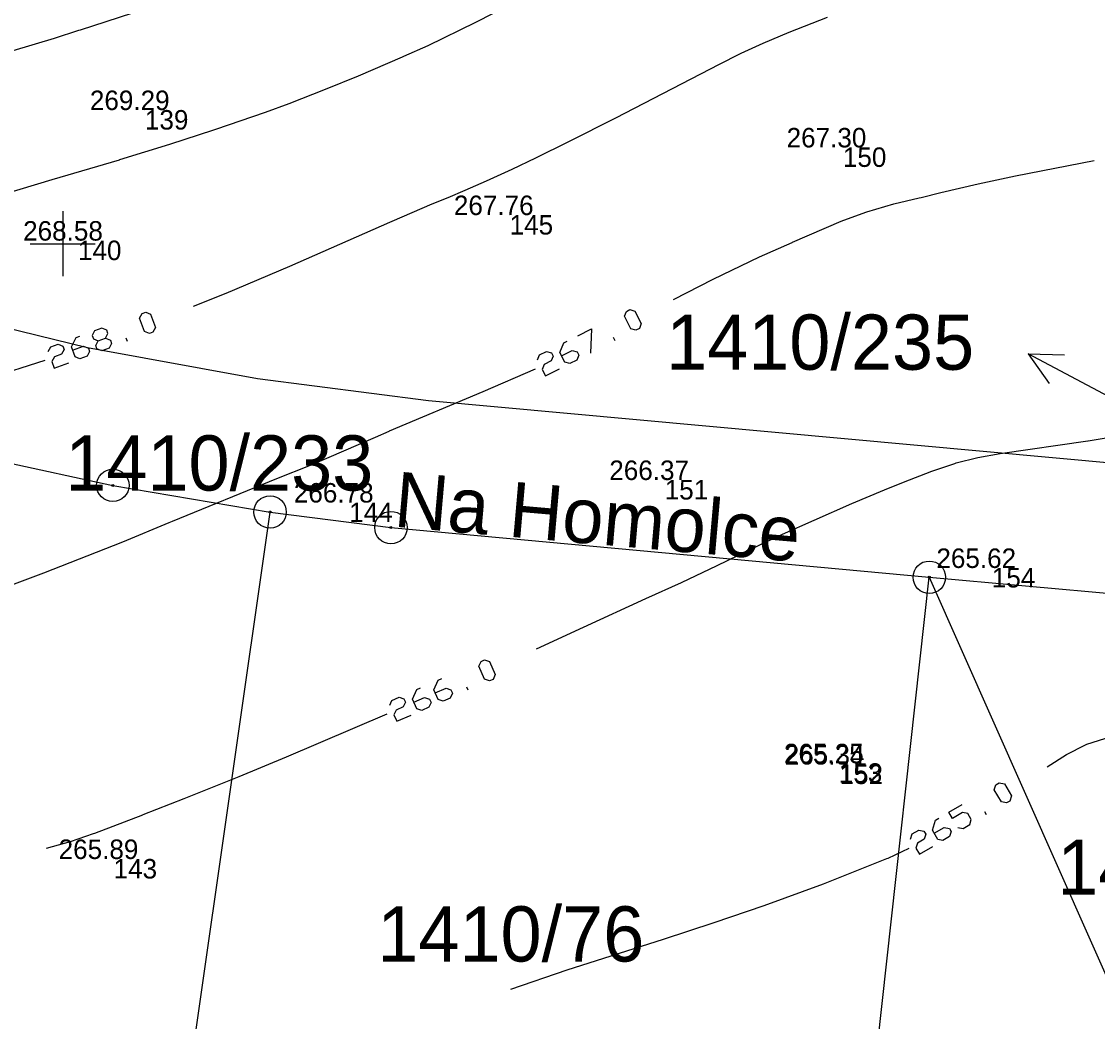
# Model space of a CAD drawing. Extents: x -771260 to -770828, y -1053564 to -1052811.
# Drawn here: x -770951.27 to -770918.15, y -1053323.95 to -1053293.16 of the extents above; entities that cross this region are included whole.
import ezdxf

# ---------------------------------------------------------------- set-up
doc = ezdxf.new("R2010")
doc.units = 0
for name, color, linetype in [('14_8_2023_krizky', 7, 'Continuous'), ('18_8_2023_vrstevnice_po_1m', 7, 'Continuous'), ('18_8_2023_zamereny_bod', 7, 'Continuous'), ('18_8_2023_zamereny_bod_cislo', 7, 'Continuous'), ('18_8_2023_zamereny_bod_vyska', 7, 'Continuous'), ('25_3_2019_krizky_JTSK', 7, 'Continuous'), ('DKM_Hranice parcel', 7, 'Continuous'), ('DKM_Parcelní čísla', 7, 'Continuous'), ('DKM_Pop  PČ popisy', 7, 'Continuous'), ('DKM_Značky bodu BP', 7, 'Continuous')]:
    doc.layers.add(name, color=color, linetype=linetype)

# ---------------------------------------------------------------- blocks, each defined once
blk = doc.blocks.new('KRIZEK')
at = {"layer": '25_3_2019_krizky_JTSK'}
for p, q in [((0, 10), (0, -10)), ((-10, 0), (10, 0))]:
    blk.add_line(p, q, dxfattribs=at)

msp = doc.modelspace()

# ---------------------------------------------------------------- linework, layer by layer
at = {"layer": '18_8_2023_vrstevnice_po_1m'}
for points in [[(-770954.285, -1053299.253), (-770952.368, -1053298.64), (-770952.307, -1053298.621), (-770950.323, -1053298.024), (-770948.256, -1053297.415), (-770948.24, -1053297.41), (-770946.707, -1053296.934), (-770945.355, -1053296.495), (-770945.287, -1053296.473), (-770943.761, -1053295.949), (-770943.036, -1053295.684), (-770941.913, -1053295.246), (-770940.902, -1053294.831), (-770939.542, -1053294.247), (-770939.501, -1053294.23), (-770938.752, -1053293.895), (-770937.285, -1053293.181), (-770934.067, -1053291.521)], [(-770951.525, -1053294.047), (-770950.258, -1053293.667), (-770949.505, -1053293.426), (-770949.459, -1053293.412), (-770946.265, -1053292.365)], [(-770945.973, -1053301.918), (-770944.976, -1053301.519), (-770943.012, -1053300.693), (-770939.938, -1053299.336), (-770939.858, -1053299.301), (-770938.632, -1053298.773), (-770938.143, -1053298.572), (-770937.614, -1053298.355), (-770936.962, -1053298.062), (-770936.173, -1053297.708), (-770935.436, -1053297.356), (-770934.425, -1053296.849), (-770932.98, -1053296.125), (-770929.788, -1053294.47), (-770929.163, -1053294.154), (-770929.12, -1053294.133), (-770928.442, -1053293.82), (-770927.644, -1053293.489), (-770926.464, -1053293.029)], [(-770949.459, -1053293.412), (-770949.459, -1053293.412)], [(-770937.285, -1053293.181), (-770937.285, -1053293.181)], [(-770950.258, -1053293.667), (-770950.258, -1053293.667)], [(-770927.644, -1053293.489), (-770927.644, -1053293.489)], [(-770938.752, -1053293.895), (-770938.752, -1053293.895)], [(-770929.12, -1053294.133), (-770929.12, -1053294.133)], [(-770928.442, -1053293.82), (-770928.442, -1053293.82)], [(-770939.501, -1053294.23), (-770939.501, -1053294.23)], [(-770929.788, -1053294.47), (-770929.788, -1053294.47)], [(-770940.902, -1053294.831), (-770940.902, -1053294.831)], [(-770941.913, -1053295.246), (-770941.913, -1053295.246)], [(-770943.036, -1053295.684), (-770943.036, -1053295.684)], [(-770943.761, -1053295.949), (-770943.761, -1053295.949)], [(-770932.98, -1053296.125), (-770932.98, -1053296.125)], [(-770945.287, -1053296.473), (-770945.287, -1053296.473)], [(-770946.707, -1053296.934), (-770946.707, -1053296.934)], [(-770948.24, -1053297.41), (-770948.24, -1053297.41)], [(-770935.436, -1053297.356), (-770935.436, -1053297.356)], [(-770931.201, -1053301.717), (-770929.979, -1053301.094), (-770928.557, -1053300.407), (-770927.556, -1053299.958), (-770927.538, -1053299.95), (-770926.04, -1053299.304), (-770925.285, -1053299.026), (-770925.248, -1053299.013), (-770924.422, -1053298.772), (-770923.644, -1053298.591), (-770923.585, -1053298.577), (-770922.98, -1053298.419), (-770921.825, -1053298.152), (-770920.676, -1053297.909), (-770918.253, -1053297.44)], [(-770936.173, -1053297.708), (-770936.173, -1053297.708)], [(-770950.323, -1053298.024), (-770950.323, -1053298.024)], [(-770920.676, -1053297.909), (-770920.676, -1053297.909)], [(-770937.614, -1053298.355), (-770937.614, -1053298.355)], [(-770922.98, -1053298.419), (-770922.98, -1053298.419)], [(-770921.825, -1053298.152), (-770921.825, -1053298.152)], [(-770938.632, -1053298.773), (-770938.632, -1053298.773)], [(-770924.422, -1053298.772), (-770924.422, -1053298.772)], [(-770923.585, -1053298.577), (-770923.585, -1053298.577)], [(-770925.248, -1053299.013), (-770925.248, -1053299.013)], [(-770939.858, -1053299.301), (-770939.858, -1053299.301)], [(-770926.04, -1053299.304), (-770926.04, -1053299.304)], [(-770927.538, -1053299.95), (-770927.538, -1053299.95)], [(-770928.557, -1053300.407), (-770928.557, -1053300.407)], [(-770943.012, -1053300.693), (-770943.012, -1053300.693)], [(-770929.979, -1053301.094), (-770929.979, -1053301.094)], [(-770944.976, -1053301.519), (-770944.976, -1053301.519)], [(-770931.201, -1053301.717), (-770931.201, -1053301.717)], [(-770945.973, -1053301.918), (-770945.973, -1053301.918)], [(-770932.362, -1053302.666), (-770932.518, -1053302.623), (-770932.713, -1053302.234), (-770932.655, -1053302.083), (-770932.548, -1053302.029), (-770932.392, -1053302.072), (-770932.197, -1053302.461), (-770932.255, -1053302.612), (-770932.362, -1053302.666)], [(-770947.336, -1053302.762), (-770947.486, -1053302.701), (-770947.635, -1053302.292), (-770947.56, -1053302.149), (-770947.447, -1053302.108), (-770947.297, -1053302.169), (-770947.148, -1053302.578), (-770947.224, -1053302.721), (-770947.336, -1053302.762)], [(-770948.685, -1053302.906), (-770948.61, -1053302.763), (-770948.647, -1053302.661), (-770948.797, -1053302.6), (-770949.022, -1053302.682), (-770949.097, -1053302.825), (-770949.06, -1053302.927), (-770948.91, -1053302.988)], [(-770934.153, -1053302.835), (-770933.725, -1053302.62), (-770933.753, -1053303.365)], [(-770949.697, -1053303.275), (-770949.36, -1053303.152), (-770949.21, -1053303.214), (-770949.173, -1053303.316), (-770949.248, -1053303.459), (-770949.473, -1053303.541), (-770949.623, -1053303.48), (-770949.735, -1053303.173), (-770949.584, -1053302.887), (-770949.472, -1053302.846)], [(-770948.685, -1053302.906), (-770948.535, -1053302.968), (-770948.498, -1053303.07), (-770948.573, -1053303.213), (-770948.798, -1053303.295), (-770948.948, -1053303.234), (-770948.985, -1053303.132), (-770948.91, -1053302.988)], [(-770948.91, -1053302.988), (-770948.685, -1053302.906)], [(-770948.011, -1053303.008), (-770948.048, -1053302.906)], [(-770934.648, -1053303.449), (-770934.327, -1053303.288), (-770934.171, -1053303.331), (-770934.122, -1053303.429), (-770934.18, -1053303.58), (-770934.394, -1053303.687), (-770934.55, -1053303.644), (-770934.697, -1053303.352), (-770934.581, -1053303.05), (-770934.474, -1053302.996)], [(-770933.004, -1053302.988), (-770933.053, -1053302.891)], [(-770950.447, -1053303.317), (-770950.372, -1053303.173), (-770950.147, -1053303.091), (-770949.997, -1053303.153), (-770949.96, -1053303.255), (-770950.035, -1053303.398), (-770950.26, -1053303.48), (-770950.335, -1053303.623), (-770950.261, -1053303.828), (-770949.811, -1053303.664)], [(-770935.388, -1053303.577), (-770935.329, -1053303.426), (-770935.115, -1053303.318), (-770934.96, -1053303.362), (-770934.911, -1053303.459), (-770934.969, -1053303.61), (-770935.183, -1053303.718), (-770935.241, -1053303.869), (-770935.143, -1053304.063), (-770934.715, -1053303.848)], [(-770974.631, -1053307.114), (-770972.984, -1053307.161), (-770971.679, -1053307.169), (-770970.125, -1053307.143), (-770969.042, -1053307.109), (-770967.711, -1053307.046), (-770966.119, -1053306.941), (-770965.025, -1053306.854), (-770963.668, -1053306.722), (-770962.316, -1053306.55), (-770962.296, -1053306.547), (-770960.548, -1053306.286), (-770959.637, -1053306.136), (-770958.795, -1053305.97), (-770958.745, -1053305.961), (-770958.079, -1053305.805), (-770956.948, -1053305.513), (-770955.247, -1053305.029), (-770952.303, -1053304.147), (-770952.291, -1053304.144), (-770950.541, -1053303.583)], [(-770951.818, -1053310.592), (-770950.586, -1053310.133), (-770948.152, -1053309.176), (-770946.723, -1053308.583), (-770946.628, -1053308.543), (-770943.415, -1053307.232), (-770942.372, -1053306.82), (-770942.326, -1053306.802), (-770940.377, -1053305.961), (-770939.957, -1053305.771), (-770939.94, -1053305.763), (-770937.065, -1053304.549), (-770935.45, -1053303.852)], [(-770937.065, -1053304.549), (-770937.065, -1053304.549)], [(-770935.422, -1053312.473), (-770933.975, -1053311.81), (-770932.052, -1053310.928), (-770930.958, -1053310.435), (-770929.86, -1053309.903), (-770928.525, -1053309.257), (-770927.849, -1053308.938), (-770926.876, -1053308.512), (-770925.71, -1053308.002), (-770924.712, -1053307.577), (-770924.123, -1053307.337), (-770923.251, -1053307), (-770922.546, -1053306.764), (-770922.508, -1053306.751), (-770921.835, -1053306.585), (-770921.146, -1053306.462), (-770918.446, -1053306.068), (-770918.439, -1053306.066), (-770915.953, -1053305.663)], [(-770940.377, -1053305.961), (-770940.377, -1053305.961)], [(-770939.94, -1053305.763), (-770939.94, -1053305.763)], [(-770918.439, -1053306.066), (-770918.439, -1053306.066)], [(-770921.835, -1053306.585), (-770921.835, -1053306.585)], [(-770921.146, -1053306.462), (-770921.146, -1053306.462)], [(-770942.326, -1053306.802), (-770942.326, -1053306.802)], [(-770923.251, -1053307), (-770923.251, -1053307)], [(-770922.508, -1053306.751), (-770922.508, -1053306.751)], [(-770943.415, -1053307.232), (-770943.415, -1053307.232)], [(-770924.123, -1053307.337), (-770924.123, -1053307.337)], [(-770924.712, -1053307.577), (-770924.712, -1053307.577)], [(-770925.71, -1053308.002), (-770925.71, -1053308.002)], [(-770946.628, -1053308.543), (-770946.628, -1053308.543)], [(-770927.849, -1053308.938), (-770927.849, -1053308.938)], [(-770948.152, -1053309.176), (-770948.152, -1053309.176)], [(-770928.525, -1053309.257), (-770928.525, -1053309.257)], [(-770950.586, -1053310.133), (-770950.586, -1053310.133)], [(-770930.958, -1053310.435), (-770930.958, -1053310.435)], [(-770932.052, -1053310.928), (-770932.052, -1053310.928)], [(-770935.422, -1053312.473), (-770935.422, -1053312.473)], [(-770936.867, -1053313.46), (-770937.021, -1053313.408), (-770937.195, -1053313.009), (-770937.128, -1053312.862), (-770937.019, -1053312.814), (-770936.866, -1053312.866), (-770936.691, -1053313.265), (-770936.758, -1053313.412), (-770936.867, -1053313.46)], [(-770939.192, -1053314.119), (-770938.863, -1053313.975), (-770938.71, -1053314.027), (-770938.666, -1053314.127), (-770938.732, -1053314.274), (-770938.952, -1053314.37), (-770939.105, -1053314.318), (-770939.236, -1053314.019), (-770939.103, -1053313.724), (-770938.994, -1053313.676)], [(-770938.534, -1053313.832), (-770938.205, -1053313.688), (-770938.052, -1053313.74), (-770938.008, -1053313.839), (-770938.074, -1053313.987), (-770938.294, -1053314.083), (-770938.447, -1053314.031), (-770938.577, -1053313.732), (-770938.445, -1053313.436), (-770938.335, -1053313.389)], [(-770937.526, -1053313.748), (-770937.569, -1053313.648)], [(-770939.938, -1053314.207), (-770939.871, -1053314.059), (-770939.652, -1053313.963), (-770939.499, -1053314.015), (-770939.455, -1053314.115), (-770939.521, -1053314.263), (-770939.741, -1053314.358), (-770939.807, -1053314.506), (-770939.72, -1053314.705), (-770939.281, -1053314.514)], [(-770919.698, -1053316.103), (-770919.111, -1053315.722), (-770918.525, -1053315.431), (-770918.486, -1053315.412), (-770917.731, -1053315.174), (-770916.951, -1053314.984), (-770915.901, -1053314.771), (-770913.248, -1053314.263), (-770911.909, -1053313.966), (-770911.895, -1053313.963)], [(-770950.5, -1053318.613), (-770949.76, -1053318.4), (-770949.056, -1053318.163), (-770949.012, -1053318.148), (-770947.536, -1053317.583), (-770947.524, -1053317.578), (-770946.263, -1053317.085), (-770944.576, -1053316.403), (-770943.112, -1053315.796), (-770940.015, -1053314.478)], [(-770918.486, -1053315.412), (-770918.486, -1053315.412)], [(-770943.112, -1053315.796), (-770943.112, -1053315.796)], [(-770919.111, -1053315.722), (-770919.111, -1053315.722)], [(-770919.698, -1053316.103), (-770919.698, -1053316.103)], [(-770944.576, -1053316.403), (-770944.576, -1053316.403)], [(-770920.951, -1053317.219), (-770921.109, -1053317.186), (-770921.33, -1053316.81), (-770921.282, -1053316.656), (-770921.179, -1053316.595), (-770921.02, -1053316.628), (-770920.8, -1053317.003), (-770920.848, -1053317.158), (-770920.951, -1053317.219)], [(-770946.263, -1053317.085), (-770946.263, -1053317.085)], [(-770922.451, -1053317.975), (-770922.292, -1053318.008), (-770922.086, -1053317.886), (-770922.038, -1053317.732), (-770922.148, -1053317.544), (-770922.307, -1053317.511), (-770922.616, -1053317.693), (-770922.727, -1053317.506), (-770922.314, -1053317.263)], [(-770947.524, -1053317.578), (-770947.524, -1053317.578)], [(-770921.57, -1053317.583), (-770921.625, -1053317.489)], [(-770923.18, -1053318.151), (-770922.871, -1053317.969), (-770922.712, -1053318.002), (-770922.657, -1053318.096), (-770922.705, -1053318.251), (-770922.911, -1053318.372), (-770923.07, -1053318.339), (-770923.235, -1053318.057), (-770923.139, -1053317.748), (-770923.036, -1053317.688)], [(-770949.012, -1053318.148), (-770949.012, -1053318.148)], [(-770923.91, -1053318.328), (-770923.862, -1053318.173), (-770923.655, -1053318.052), (-770923.497, -1053318.085), (-770923.442, -1053318.179), (-770923.49, -1053318.333), (-770923.696, -1053318.455), (-770923.744, -1053318.609), (-770923.634, -1053318.797), (-770923.221, -1053318.554)], [(-770950.5, -1053318.613), (-770950.5, -1053318.613)], [(-770949.76, -1053318.4), (-770949.76, -1053318.4)], [(-770936.208, -1053322.947), (-770934.475, -1053322.361), (-770931.513, -1053321.41), (-770929.949, -1053320.898), (-770928.415, -1053320.375), (-770926.582, -1053319.712), (-770924.639, -1053318.933), (-770924.6, -1053318.917), (-770923.954, -1053318.607)], [(-770924.6, -1053318.917), (-770924.6, -1053318.917)], [(-770926.582, -1053319.712), (-770926.582, -1053319.712)], [(-770928.415, -1053320.375), (-770928.415, -1053320.375)], [(-770929.949, -1053320.898), (-770929.949, -1053320.898)], [(-770931.513, -1053321.41), (-770931.513, -1053321.41)], [(-770934.475, -1053322.361), (-770934.475, -1053322.361)], [(-770936.208, -1053322.947), (-770936.208, -1053322.947)]]:
    msp.add_lwpolyline(points, dxfattribs=at)
at = {"layer": '18_8_2023_zamereny_bod'}
for p, q in [((-770947.472, -1053295.885), (-770947.472, -1053295.885)), ((-770925.99, -1053297.035), (-770925.99, -1053297.035)), ((-770936.247, -1053299.118), (-770936.247, -1053299.118)), ((-770949.533, -1053299.904), (-770949.533, -1053299.904)), ((-770931.475, -1053307.275), (-770931.475, -1053307.275)), ((-770941.183, -1053307.969), (-770941.183, -1053307.969)), ((-770921.407, -1053309.983), (-770921.407, -1053309.983)), ((-770926.116, -1053315.997), (-770926.116, -1053315.997)), ((-770926.092, -1053316.036), (-770926.092, -1053316.036)), ((-770948.436, -1053318.944), (-770948.436, -1053318.944))]:
    msp.add_line(p, q, dxfattribs=at)
at = {"layer": 'DKM_Hranice parcel'}
for p, q in [((-770938.74, -1053304.83), (-770910.45, -1053307.41)), ((-770947.02, -1053332.05), (-770943.62, -1053308.26)), ((-770925.69, -1053331.62), (-770923.33, -1053310.27)), ((-770923.33, -1053310.27), (-770911.93, -1053311.29)), ((-770923.33, -1053310.27), (-770914.09, -1053331.12))]:
    msp.add_line(p, q, dxfattribs=at)
for points in [[(-770987.56, -1053285.59), (-770984.56, -1053287.74), (-770983.25, -1053288.69), (-770981.02, -1053290.15), (-770978.77, -1053291.54), (-770975.07, -1053293.62), (-770974.14, -1053294.15), (-770969.37, -1053296.5), (-770964.48, -1053298.58), (-770959.49, -1053300.4), (-770954.4, -1053301.93), (-770949.24, -1053303.19), (-770944.01, -1053304.15), (-770938.74, -1053304.83)], [(-770965.04, -1053302.65), (-770962.01, -1053303.78), (-770958.66, -1053304.87), (-770955.3, -1053305.85), (-770951.86, -1053306.71), (-770948.46, -1053307.44), (-770943.62, -1053308.26)], [(-770943.62, -1053308.26), (-770939.9, -1053308.74), (-770923.33, -1053310.27)]]:
    msp.add_lwpolyline(points, dxfattribs=at)
at = {"layer": 'DKM_Pop  PČ popisy'}
for p, q in [((-770917.64, -1053304.8), (-770920.29, -1053303.391)), ((-770920.29, -1053303.391), (-770919.17, -1053303.419)), ((-770920.29, -1053303.391), (-770919.641, -1053304.303))]:
    msp.add_line(p, q, dxfattribs=at)
at = {"layer": 'DKM_Značky bodu BP'}
for centre, radius in [((-770948.46, -1053307.44), 0.5), ((-770948.46, -1053307.44), 0.0303), ((-770943.62, -1053308.26), 0.5), ((-770943.62, -1053308.26), 0.0303), ((-770939.9, -1053308.74), 0.5), ((-770939.9, -1053308.74), 0.0303), ((-770923.33, -1053310.27), 0.5), ((-770923.33, -1053310.27), 0.0303)]:
    msp.add_circle(centre, radius, dxfattribs=at)

# ---------------------------------------------------------------- block references
at = {"layer": '14_8_2023_krizky', "xscale": 0.1, "yscale": 0.10000000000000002}
msp.add_blockref('KRIZEK', (-770950, -1053300), dxfattribs=at)

# ---------------------------------------------------------------- texts
at = {"layer": '18_8_2023_zamereny_bod_cislo'}
for s, p in [('139', (-770947.472, -1053296.485)), ('150', (-770925.99, -1053297.635)), ('145', (-770936.247, -1053299.718)), ('140', (-770949.533, -1053300.504)), ('151', (-770931.475, -1053307.875)), ('144', (-770941.183, -1053308.569)), ('154', (-770921.407, -1053310.583)), ('153', (-770926.116, -1053316.597)), ('152', (-770926.092, -1053316.636)), ('143', (-770948.436, -1053319.544))]:
    msp.add_text(s, height=0.6, dxfattribs=at).set_placement(p)
at = {"layer": '18_8_2023_zamereny_bod_vyska'}
for s, p in [('269.29 ', (-770949.166, -1053295.885)), ('267.30 ', (-770927.722, -1053297.035)), ('267.76 ', (-770937.963, -1053299.118)), ('268.58 ', (-770951.221, -1053299.904)), ('266.37 ', (-770933.18, -1053307.275)), ('266.78 ', (-770942.888, -1053307.969)), ('265.62 ', (-770923.112, -1053309.983)), ('265.25 ', (-770927.804, -1053315.997)), ('265.34 ', (-770927.78, -1053316.036)), ('265.89 ', (-770950.128, -1053318.944))]:
    msp.add_text(s, height=0.6, dxfattribs=at).set_placement(p)
at = {"layer": 'DKM_Parcelní čísla'}
for s, p in [('1410/235', (-770931.431, -1053303.88)), ('1410/233', (-770949.925, -1053307.6)), ('1410/236', (-770919.391, -1053320.044)), ('1410/76', (-770940.32, -1053322.1))]:
    msp.add_text(s, height=1.7, dxfattribs=at).set_placement(p)
at = {"layer": 'DKM_Pop  PČ popisy'}
msp.add_text('Na Homolce', height=1.7, rotation=355, dxfattribs=at).set_placement((-770939.84, -1053308.707))

doc.saveas('drawing.dxf')
